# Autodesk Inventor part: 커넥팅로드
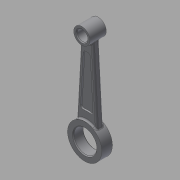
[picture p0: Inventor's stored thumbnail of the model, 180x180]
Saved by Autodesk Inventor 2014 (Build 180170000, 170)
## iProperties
Created: 2016-11
Part Number: 커넥팅로드
Material: 일반
Document SubType Name: Modeling
Designer: mduedu
Density: 1 g/cm^3
Appearance: 기본값
Mass: 23.9068 g
Surface Area: 114.14 cm^2
Volume: 23.9068 cm^3
Author: mduedu
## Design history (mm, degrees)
sketch "스케치1" dims "d0" = 42, "d3" = 20
  geometry: L1 (0, 0)-(0, 114); L2 (-7.5, 107.386)-(-12.5, 16.875); L3 (7.5, 107.386)-(12.5, 16.875); C1 r 14 at (0, 0); C2 r 6.5 at (0, 114); 3 further points
  constraints: 6 end point, 4 coincident, 2 centre point, 2 symmetric about line, 1 vertical, 6 other
  dimensions: "d1" = 28 diameter of C1; "d2" = 13 diameter of C2; "d4" = 114 distance of L1.start L1.end; "d6" = 12.5 distance from line of L1 L2.end; "d7" = 7.5 distance from line of L1 L2.start
extrude "돌출1" new body sketch "스케치1" stored distance "d8" = 13; taper "d9" = 0 deg
extrude "돌출2" join sketch "스케치1" stored distance "d10" = 20; taper "d11" = 0 deg
sketch "스케치2"
  geometry: L1 (-7.5, 107.386)-(-12.5, 16.875) reference; L2 (7.5, 107.386)-(12.5, 16.875) reference; A1 r 10 centre (0, 114) between (-7.5, 107.386) and (7.5, 107.386) reference; A2 r 21 centre (0, 0) between (-12.5, 16.875) and (12.5, 16.875) reference; 1 further point
extrude "돌출3" join sketch "스케치2" stored distance "d12" = 8; taper "d13" = 0 deg
sketch "스케치3"
  geometry: L1 (-7.5, 107.386)-(-12.5, 16.875) reference; L2 (7.5, 107.386)-(12.5, 16.875) reference; L3 (-4.209, 94.448)-(-7.768, 30.011); L4 (4.209, 94.448)-(7.768, 30.011); L5 (0, 94)-(0, 31); A1 r 10 centre (0, 114) between (-7.5, 107.386) and (7.5, 107.386) reference; A2 r 21 centre (0, 0) between (-12.5, 16.875) and (12.5, 16.875) reference; A3 r 20 centre (0, 114) between (-4.209, 94.448) and (4.209, 94.448); A4 r 31 centre (0, 0) between (7.768, 30.011) and (-7.768, 30.011); 1 further point
  constraints: 6 end point, 6 point on circle, 2 centre point, 2 parallel, 1 symmetric about line, 1 vertical alignment
  dimensions: "d18" = 10 radial gap between concentric circles of A3 A1; "d19" = 10 radial gap between concentric circles of A2 A4; "d20" = 4 distance between parallel lines of L3 L1
extrude "돌출4" cut sketch "스케치3" distance "d21" = 2; taper "d22" = 0 deg
fillet "모깎기1" dims "d23" = 3
fillet "모깎기2" dims "d24" = 2
fillet "모깎기3" dims "d25" = 2
chamfer "모따기1" distance "d26" = 1; stored, may be unused: second distance "d27" = 2, angle "d28" = 45 deg
node "솔리드1"
mirror "대칭1"
other parameters: "d16" = 4, "d17" = 4
